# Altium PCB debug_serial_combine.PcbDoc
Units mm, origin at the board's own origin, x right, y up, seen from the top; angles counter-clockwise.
Board outline 24.45 x 22.13 mm, 2 copper layers (Top Layer, Bottom Layer); 2 components, 7 nets, 14 pads, 0 vias.
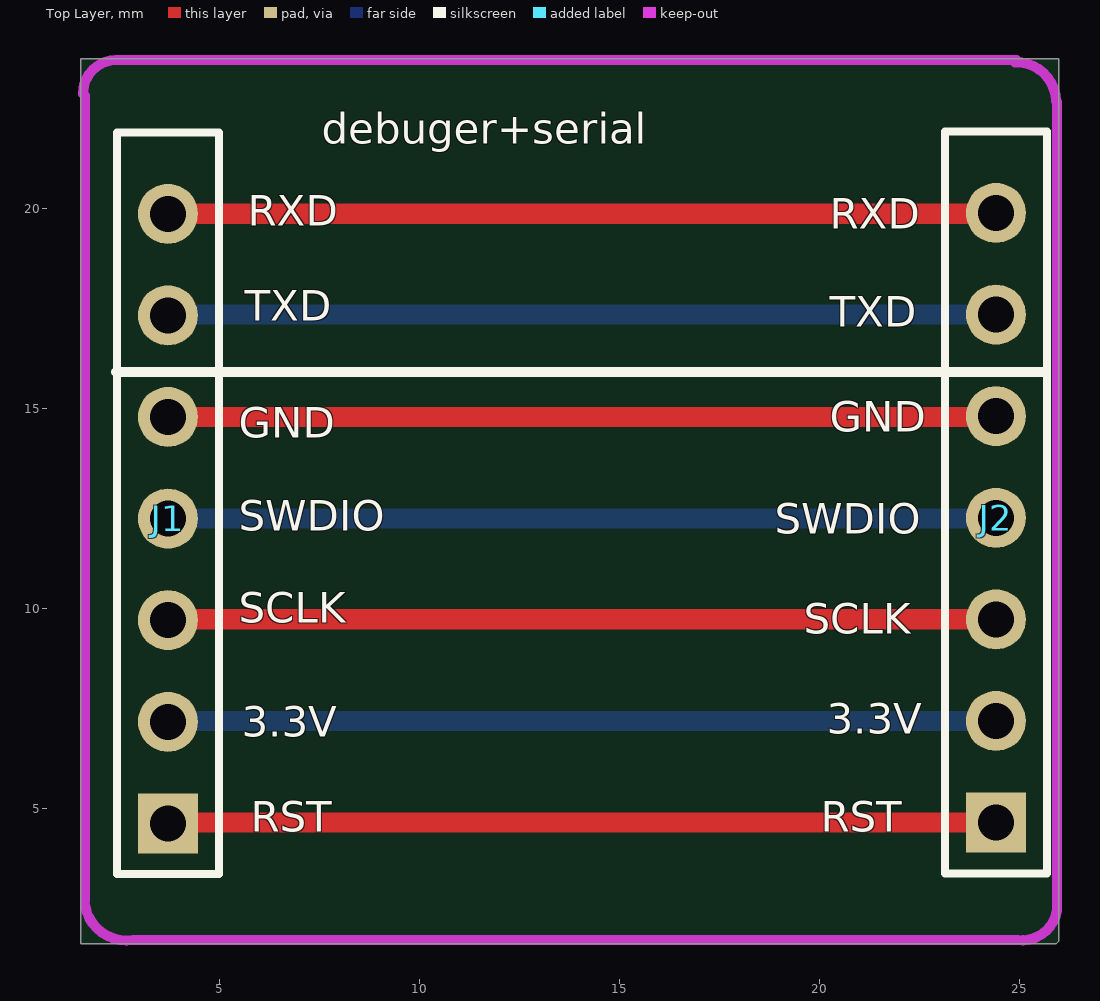
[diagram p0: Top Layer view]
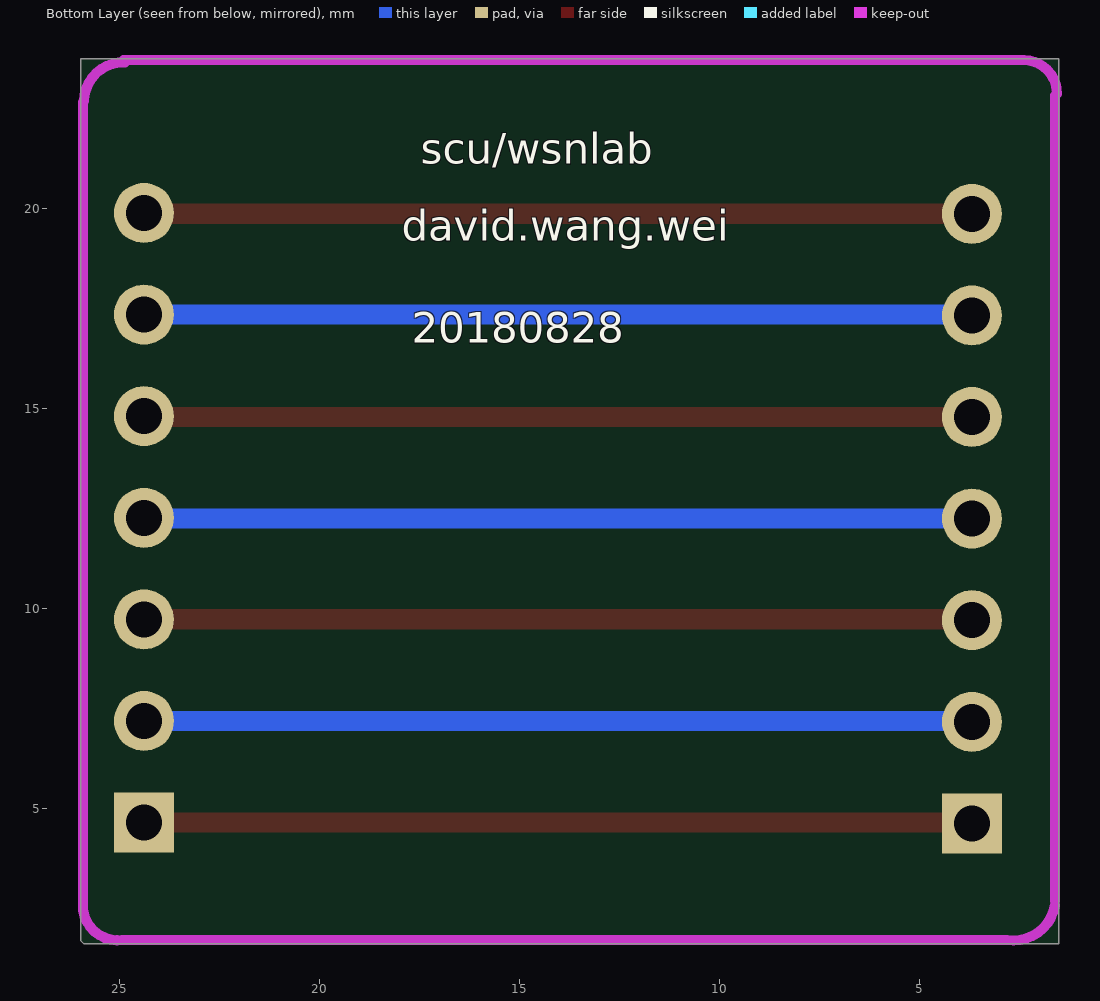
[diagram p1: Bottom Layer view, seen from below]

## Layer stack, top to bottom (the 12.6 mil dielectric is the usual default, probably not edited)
Top Solder: solder mask 0.0102, Solder Resist, Dk 3.5
Top Layer: signal copper 0.0356
Dielectric 1: dielectric 0.32, FR-4, Dk 4.8
Bottom Layer: signal copper 0.0356
Bottom Solder: solder mask 0.0102, Solder Resist, Dk 3.5

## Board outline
25.9,1.625 25.975,1.7 25.975,23.75 1.525,23.75 1.525,1.625

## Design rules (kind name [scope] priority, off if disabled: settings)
Clearance Clearance_1 [InPolygon] p1: gap=0.508 ignorepadtopadclearanceinfootprint=FALSE except(0: Arc-Hole Track-Hole SMDPad-Hole THPad-Hole Via-Hole Fill-Hole Poly-Hole Region-Hole Text-Hole)
Clearance [All] p2: gap=0.178 ignorepadtopadclearanceinfootprint=FALSE except(0: Arc-Hole Track-Hole SMDPad-Hole THPad-Hole Via-Hole Fill-Hole Poly-Hole Region-Hole Text-Hole)
ComponentClearance [All] p1: gap=0.102 collisioncheckmode=3 verticalgap=0.102 showdistances=FALSE
DiffPairsRouting [All] p1: maxlimit=0.254 minlimit=0.254 mostfreqgap=0.254 toplayer_minwidth=0.254 toplayer_maxwidth=0.381 toplayer_prefwidth=0.381 bottomlayer_minwidth=0.254 bottomlayer_maxwidth=0.381 bottomlayer_prefwidth=0.381 maxuncoupledlength=12.7
HoleSize [All] p1: absolutevalues=TRUE maxlimit=12.7 minlimit=0.025 maxpercent=80.000 minpercent=20.000
HoleToHoleClearance [All] p1: gap=0.102 allowstackedmicrovias=TRUE
MinimumSolderMaskSliver [All] p1: minsoldermaskwidth=0.102
PolygonConnect PolygonConnect_1 [Isvia] p1: connectstyle=Direct reliefconductorwidth=0.254 reliefentries=4 polygonreliefangle="90 Angle" airgapwidth=0.254
PolygonConnect [All] p2: connectstyle=Relief reliefconductorwidth=0.508 reliefentries=4 polygonreliefangle="90 Angle" airgapwidth=0.254
RoutingVias [All] p1: holewidth=0.508 width=0.762 viastyle="Through Hole" minholewidth=0.254 minwidth=0.254 maxholewidth=0.711 maxwidth=1.27
SilkToSilkClearance [All] p1: silktosilkclearance=0.102
SilkToSolderMaskClearance [IsPad] p1: minsilkscreentomaskgap=0 clearancetoexposedcopper=TRUE
SolderMaskExpansion [All] p1: expansion=0.102
Width [All] p1: maxlimit=12.7 minlimit=0.254 preferedwidth=0.254 minimp=50.000000 maximp=50.000000 favimp=50.000000
23 further rules are at their usual default settings.

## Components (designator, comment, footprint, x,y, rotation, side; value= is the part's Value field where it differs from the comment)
J1 "4P/NC" HDR1X7 3.7,4.64 r90 top
J2 "4P/NC" HDR1X7 24.4,4.66 r90 top

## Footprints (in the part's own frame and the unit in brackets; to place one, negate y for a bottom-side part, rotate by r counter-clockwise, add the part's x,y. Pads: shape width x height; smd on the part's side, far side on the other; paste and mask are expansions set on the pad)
HDR1X7 [mm]
  rect 1.5x1.5 hole 0.9: 1(0,0)
  round 1.5 hole 0.9: 2(2.54,0) 3(5.08,0) 4(7.62,0) 5(10.16,0) 6(12.7,0) 7(15.24,0)
  silkscreen extent -1.27,-1.27 17.27,1.27

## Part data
J1 J2: library part "Header 7", "接口"

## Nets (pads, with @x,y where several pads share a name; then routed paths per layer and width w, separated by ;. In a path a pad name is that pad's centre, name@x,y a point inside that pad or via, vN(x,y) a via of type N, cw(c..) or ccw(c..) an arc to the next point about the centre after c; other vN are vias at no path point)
NetJ1_1: J1.1 J2.1 | length 20.7
  Top Layer w0.508: J1.1 3.72,4.66 J2.1
NetJ1_2: J1.2 J2.2 | length 20.7
  Bottom Layer w0.508: J1.2 3.72,7.2 J2.2
NetJ1_3: J1.3 J2.3 | length 20.7
  Top Layer w0.508: J1.3 3.72,9.74 J2.3
NetJ1_4: J1.4 J2.4 | length 20.7
  Bottom Layer w0.508: J1.4 24.38,12.26 J2.4
NetJ1_5: J1.5 J2.5 | length 20.7
  Top Layer w0.508: J1.5 24.38,14.8 J2.5
NetJ1_6: J1.6 J2.6 | length 20.7
  Bottom Layer w0.508: J1.6 3.72,17.36 J2.6
NetJ1_7: J1.7 J2.7 | length 20.7
  Top Layer w0.508: J1.7 24.38,19.88 J2.7

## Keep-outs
Keep-Out Layer:
  lines w0.254: 0,80.975 64,80.975 64,-0.358 ; 1.625,2.6 ccw(c2.662,2.762) 2.825,1.725 24.95,1.725 ; 1.625,2.7 1.625,22.832 1.575,22.882 cw(c2.405,22.891) 2.397,23.721 ; 2.397,23.725 24.906,23.725 ; 24.881,23.67 cw(c24.906,22.675) 25.9,22.7 25.925,22.675 25.925,2.475 cw(c25.05,2.6) 24.925,1.725

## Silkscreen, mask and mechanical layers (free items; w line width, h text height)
Top Overlay:
  lines w0.254: 2.4,15.925 25.625,15.925
  text "debuger+serial" at 7.55,21.625 h0.76
  text "RXD" at 5.7,19.575 h0.76
  text "RXD" at 20.25,19.5 h0.76
  text "TXD" at 5.625,17.2 h0.76
  text "TXD" at 20.25,17.05 h0.76
  text "GND" at 20.25,14.425 h0.76
  text "GND" at 5.475,14.275 h0.76
  text "SWDIO" at 5.475,11.95 h0.76
  text "SWDIO" at 18.875,11.875 h0.76
  text "SCLK" at 5.475,9.65 h0.76
  text "SCLK" at 19.6,9.375 h0.76
  text "3.3V" at 20.175,6.875 h0.76
  text "3.3V" at 5.55,6.8 h0.76
  text "RST" at 5.775,4.425 h0.76
  text "RST" at 20.025,4.425 h0.76
Bottom Overlay:
  text "scu/wsnlab" at 17.475,21.125 h0.76
  text "david.wang.wei" at 17.95,19.2 h0.76
  text "20180828" at 17.7,16.65 h0.76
